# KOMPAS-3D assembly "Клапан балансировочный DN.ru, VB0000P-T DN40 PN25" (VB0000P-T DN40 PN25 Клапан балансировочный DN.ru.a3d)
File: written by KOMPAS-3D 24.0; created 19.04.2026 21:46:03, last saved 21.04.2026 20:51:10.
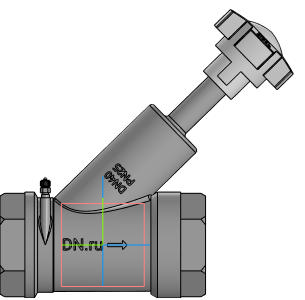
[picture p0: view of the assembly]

Document properties: Автор: DN.ru; Полное имя файла: C:\Работа\VB0000P-T DN X PN 25 Клапан балансировочный DN.ru\DN40\исходные материалы\VB0000P-T DN40 PN25 Клапан балансировочный DN.ru.a3d

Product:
- Component [detail]: Деталь  | qty 1  | pos. 1  | Масса: 0.00084; Раздел спецификации: Прочие изделия; Примечание: D080-01177; Автор: mrdid; source file: VB0000P-T DN40 PN25 Клапан балансировочный DN.ru.m3d
- Component [detail]: Деталь2  | qty 1  | pos. 2  | Масса: 0.358794; Автор: tyuri; additional columns: Типовые; source file: Деталь2 - Деталь2.m3d
- Part/product: Клапан балансировочный DN.ru  | designation VB0000P-T DN40 PN25
    Масса: 1.2
    Раздел спецификации: Прочие изделия
    Примечание: D080-01179

Referenced files in C:\Работа\VB0000P-T DN X PN 25 Клапан балансировочный DN.ru\DN40\исходные материалы\: Деталь2 - Деталь2.m3d, VB0000P-T DN40 PN25 Клапан балансировочный DN.ru.m3d
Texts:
  VB0000P-T DN40 PN25
  Деталь2 Деталь2
  Плоскость XY.Начало координат
  Плоскость ZY.Начало координат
